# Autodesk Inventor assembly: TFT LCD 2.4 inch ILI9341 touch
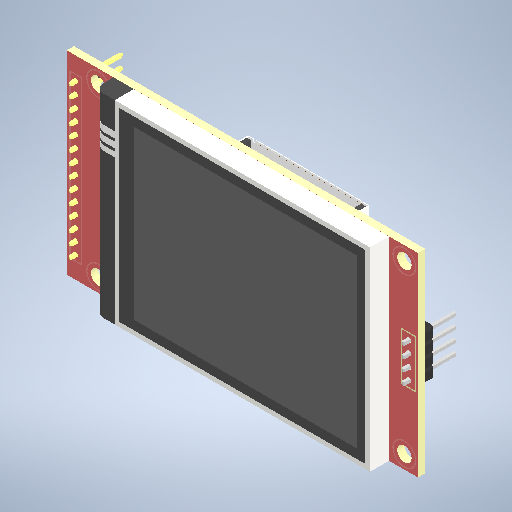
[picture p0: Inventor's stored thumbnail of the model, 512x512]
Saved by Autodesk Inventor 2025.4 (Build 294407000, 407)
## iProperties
Created: 2025-06
Part Number: TFT LCD 2.4 inch ILI9341 touch
Description: Designed by EasyEDA Pro
Document SubType Name: Assembly
Designer: Marcio Valenzuela
Title: TFT LCD 2.4 inch ILI9341.step
Sending System: Autodesk Translation Framework v14.10.0.0
Preprocessor: ST-DEVELOPER v20.1
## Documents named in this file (13)
- C:\Users\Marcio Valenzuela\OneDrive\Documentos\TFT LCD 2.4 inch ILI9341 touch.iam
- C:\Users\Marcio Valenzuela\Downloads\tft-lcd-2-4-inch-ili9341-touch-320x240-1.snapshot.15\TFT LCD 2.4 inch ILI9341 touch\TFT LCD 2.4 inch ILI9341 touch\Board~HwOR.ipt
- C:\Users\Marcio Valenzuela\Downloads\tft-lcd-2-4-inch-ili9341-touch-320x240-1.snapshot.15\TFT LCD 2.4 inch ILI9341 touch\TFT LCD 2.4 inch ILI9341 touch\TopSilkscreen~HwOR.ipt
- C:\Users\Marcio Valenzuela\Downloads\tft-lcd-2-4-inch-ili9341-touch-320x240-1.snapshot.15\TFT LCD 2.4 inch ILI9341 touch\TFT LCD 2.4 inch ILI9341 touch\BottomSilkscreen~HwOR.ipt
- C:\Users\Marcio Valenzuela\Downloads\tft-lcd-2-4-inch-ili9341-touch-320x240-1.snapshot.15\TFT LCD 2.4 inch ILI9341 touch\TFT LCD 2.4 inch ILI9341 touch\R1~R0603~R0603~HwOR.iam
- C:\Users\Marcio Valenzuela\Downloads\tft-lcd-2-4-inch-ili9341-touch-320x240-1.snapshot.15\TFT LCD 2.4 inch ILI9341 touch\TFT LCD 2.4 inch ILI9341 touch\C1~C0603~C0603_L1.6-W0.8-H0.8~HwOR.iam
- C:\Users\Marcio Valenzuela\Downloads\tft-lcd-2-4-inch-ili9341-touch-320x240-1.snapshot.15\TFT LCD 2.4 inch ILI9341 touch\TFT LCD 2.4 inch ILI9341 touch\H2~HDR-TH_4P-P2.54-V-M~HDR-TH_4P-P2.54-M-LI-1X4P~HwOR.iam
- C:\Users\Marcio Valenzuela\Downloads\tft-lcd-2-4-inch-ili9341-touch-320x240-1.snapshot.15\TFT LCD 2.4 inch ILI9341 touch\TFT LCD 2.4 inch ILI9341 touch\H3~CONN-TH_PZ254V-11-14P~CONN-TH_PZ254V-11-14P~HwOR.iam
- C:\Users\Marcio Valenzuela\Downloads\tft-lcd-2-4-inch-ili9341-touch-320x240-1.snapshot.15\TFT LCD 2.4 inch ILI9341 touch\TFT LCD 2.4 inch ILI9341 touch\Q1~SOT-23-3_L2.9-W1.3-P1.90-LS2.4-BR~SOT-23-3P_L2.9-W1.3-H.iam
- C:\Users\Marcio Valenzuela\Downloads\tft-lcd-2-4-inch-ili9341-touch-320x240-1.snapshot.15\TFT LCD 2.4 inch ILI9341 touch\TFT LCD 2.4 inch ILI9341 touch\U1~SD-CARD-SMD_SD-CARD-11P~SD-CARD-SMD_SD-CARD-11P~HwOR.iam
- C:\Users\Marcio Valenzuela\Downloads\tft-lcd-2-4-inch-ili9341-touch-320x240-1.snapshot.15\TFT LCD 2.4 inch ILI9341 touch\TFT LCD 2.4 inch ILI9341 touch\U2~TSSOP-16_L5.0-W4.4-P0.65-LS6.4-BL~TSSOP-16_L5.0-W4.4-H1.iam
- C:\Users\Marcio Valenzuela\Downloads\tft-lcd-2-4-inch-ili9341-touch-320x240-1.snapshot.15\TFT LCD 2.4 inch ILI9341 touch\TFT LCD 2.4 inch ILI9341 touch\text.ipt
- C:\Users\Marcio Valenzuela\Downloads\tft-lcd-2-4-inch-ili9341-touch-320x240-1.snapshot.15\TFT LCD 2.4 inch ILI9341 touch\TFT LCD 2.4 inch ILI9341 touch\Part24.ipt
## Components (19 placed, 12 different names)
1. Board~HwOR:1
2. TopSilkscreen~HwOR:1
3. BottomSilkscreen~HwOR:1
4. R1~R0603~R0603~HwOR:1 [sub-assembly]
5. C1~C0603~C0603_L1.6-W0.8-H0.8~HwOR:1 [sub-assembly]
6. H2~HDR-TH_4P-P2.54-V-M~HDR-TH_4P-P2.54-M-LI-1X4P~HwOR:1 [sub-assembly]
7. H3~CONN-TH_PZ254V-11-14P~CONN-TH_PZ254V-11-14P~HwOR:1 [sub-assembly]
8. Q1~SOT-23-3_L2.9-W1.3-P1.90-LS2.4-BR~SOT-23-3P_L2.9-W1.3-H1.0-LS2.4-P0.95~HwOR:1 [sub-assembly]
9. U1~SD-CARD-SMD_SD-CARD-11P~SD-CARD-SMD_SD-CARD-11P~HwOR:1 [sub-assembly]
10. U2~TSSOP-16_L5.0-W4.4-P0.65-LS6.4-BL~TSSOP-16_L5.0-W4.4-H1.0-LS6.4-P0.65~HwOR:1 [sub-assembly]
11. R1~R0603~R0603~HwOR:2 [sub-assembly]
12. R1~R0603~R0603~HwOR:3 [sub-assembly]
13. R1~R0603~R0603~HwOR:4 [sub-assembly]
14. R1~R0603~R0603~HwOR:5 [sub-assembly]
15. R1~R0603~R0603~HwOR:6 [sub-assembly]
16. C1~C0603~C0603_L1.6-W0.8-H0.8~HwOR:2 [sub-assembly]
17. Q1~SOT-23-3_L2.9-W1.3-P1.90-LS2.4-BR~SOT-23-3P_L2.9-W1.3-H1.0-LS2.4-P0.95~HwOR:2 [sub-assembly]
18. text:1
19. Part24
